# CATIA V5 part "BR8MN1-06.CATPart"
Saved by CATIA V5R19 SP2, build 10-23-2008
Part number: BR8MN1-06
Definition: design
Nomenclature: BR8MN1-06
Source: Unknown
Bounding box of the stored display mesh (mm): x -4.6 to 7.9, y 0 to 12, z 0 to 30.48
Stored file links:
  Z:\fausse table rondelle-20220905T211342Z-001\fausse table rondelle\BR8MN1-06.CATPart
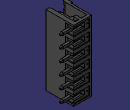
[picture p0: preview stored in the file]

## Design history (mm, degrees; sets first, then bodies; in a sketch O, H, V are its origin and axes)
AxisSystem1: origin (0, 0, 0), X (1, 0, 0), Y (0, 1, 0), Z (0, 0, 1)
Body1 "MANIFOLD_SOLID_BREP #202339" (main body)
  Solid1: solid without history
